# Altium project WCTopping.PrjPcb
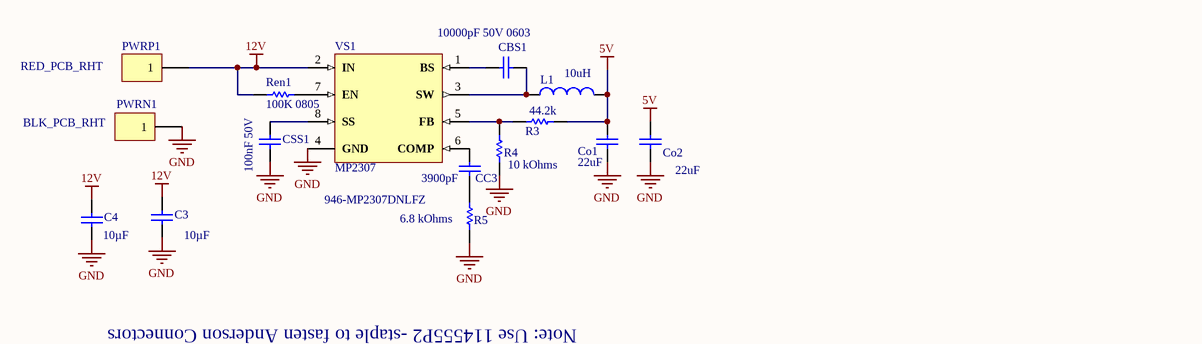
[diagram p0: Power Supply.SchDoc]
Project_Name: WC Topping; Revision: 1.2
5 sheets, 59 parts. Net scope: flat (ports and power ports of the same name join across sheets).
Board file: WCTopping.PcbDoc
Sheets:
  Power Supply.SchDoc
  Processor_Interface.SchDoc
  CAN_Interface.SchDoc
  Digital_IO.SchDoc
  Relay_IO.SchDoc

## Sheet Power Supply.SchDoc: Power Supply 5V @ 3A
size A; Engineer: H Potential; DocumentNumber: 5; Revision: 3.2; SheetNumber: 5; SheetTotal: 5

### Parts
C3  10µF  [CAPC2013X135X45ML10T25]
C4  10µF  [CAPC2013X135X45ML10T25]
CBS1  10000pF 50V 0603  [0603C_L]
CC3  3900pF  [0603C_L]
Co1  22uF  [0603C_L]
Co2  22uF  [0603C_L]
CSS1  100nF 50V  [0603C_L]
L1  10uH  [IND_1]
PWRN1  BLK_PCB_RHT  [Anderson_BLK_RHT_BOT]
PWRP1  RED_PCB_RHT  [Anderson_Red_RHT_BOT]
R3  44.2k  [0805_L]
R4  10 kOhms  [0805_L]
R5  6.8 kOhms  [0805_L]
Ren1  100K 0805  [0805_L]
VS1  MP2307  Supplier Part Number 1: 946-MP2307DNLFZ  [SOIC8N_EXP]

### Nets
5V: Co1.2 Co2.2 L1.2 R3.1
12V: C3.2 C4.2 PWRP1.1 Ren1.1 VS1.2(IN)
GND: C3.1 C4.1 Co1.1 Co2.1 CSS1.1 PWRN1.1 R4.2 R5.1 VS1.4(GND)
NetCBS1_1: CBS1.1 L1.1 VS1.3(SW)
NetCBS1_2: CBS1.2 VS1.1(BS)
NetCC3_1: CC3.1 R5.2
NetCC3_2: CC3.2 VS1.6(COMP)
NetCSS1_2: CSS1.2 VS1.8(SS)
NetR3_2: R3.2 R4.1 VS1.5(FB)
NetRen1_2: Ren1.2 VS1.7(EN)

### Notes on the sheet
- Note: Use 114555P2 -staple to fasten Anderson Connectors

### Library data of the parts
C3 C4 = CMP-2007-03541-1: Part Number: GRM21BR61E106KA73L; Manufacturer: Murata; Product Training Modules: High-Cap Multilayer Ceramic Capacitors; Catalog Drawings: GRM Series_0805_1.25; Tolerance: ±10%; Voltage - Rated: 25V; Temperature Coefficient: X5R; Online Catalog: GRM Series; Other Names: 490-5523-6
CBS1 = Cap10000pF_50V_0603: Manufacturer: Yageo; Manufacturer Part Number: CC0603KRX7R9BB103; Product Training Modules: Multilayer Ceramic Capacitors; Featured Product: Commodity Multilayer Ceramic Capacitors – CC Series; Tolerance: ±10%; Temperature Coefficient: X7R; Online Catalog: CC Series; Other Names: 311-1085-6
CC3 = Cap_0603_1: Manufacturer: Murata; Manufacturer Part Number: GRM188R71E392KA01D; Tolerance (+ or -): 10%; Voltage: 25VDC; Temp Coeff (Dielectric): X7R; Case Style: Ceramic Chip; Wire Form: Not Required; Product Length (mm): 1.6mm; Product Depth (mm): 0.8mm; Product Diameter (mm): Not Requiredmm
Co1 Co2 = Cap_0603_1: Manufacturer: Murata; Manufacturer Part Number: GRM188R60J226MEA0D; Tolerance (+ or -): 20%; Voltage: 6.3VDC; Temp Coeff (Dielectric): X5R; Case Style: Ceramic Chip; Wire Form: Not Required; Product Length (mm): 1.6mm; Product Depth (mm): 0.8mm; Product Diameter (mm): Not Requiredmm
CSS1 = Cap100nF_50V_0603: Manufacturer: Yageo; Manufacturer Part Number: CC0603ZRY5V9BB104; Capacitance: 0.10µF; Tolerance: -20%, +80%; Temperature Coefficient: Y5V (F)
L1 = Inductor: Manufacturer: Abracon; Manufacturer Part Number: ASPI-0630LR-100M-T15; Code_IEC: 1005; Rad Hard: No; Type: Power; Maximum DC Current: 4 A; Tolerance: 20 %; Maximum DC Resistance: 68 mOhm; Product Depth: 6.65 mm; Product Height: 3(Max) mm
PWRN1 = Anderson-1Pin BLK_PCB_RHT: 1 pin Anderson; Manufacturer: Anderson Power Products (APP); Manufacturer Part Number: 1377G1, 1377G2, 1327-BK,137G6-BK; Number of Positions / Contacts: 1; Voltage Rating: 600 V; Current Rating: 25 A
PWRP1 = Anderson-1Pin RED_PCB_RHT: 1 pin Anderson; Manufacturer: Anderson Power Products (APP); Manufacturer Part Number: 1377G1, 1377G2, 1327-BK,137G6-BK; Number of Positions / Contacts: 1; Voltage Rating: 600 V; Current Rating: 25 A
R3 = Res_0805: Manufacturer: Yageo; Manufacturer Part Number: RC0805FR-0744K2L; Product Training Modules: Chip Resistor; Catalog Drawings: Thick Film Resistor Side; PCN Other: RC/AC 0603/0805/1206 22/Jan/2013; HTML Datasheet: RC Series, L Suffix Datasheet.html; EDA / CAD Models: Download from Accelerated Designs; Tolerance: ±1%; Power (Watts): 0.125W, 1/8W; Temperature Coefficient: ±100ppm/°C; Online Catalog: RC0805 Series; Kits: PHC5A-KIT-ND  - RESISTOR KIT 10K-97.6K 1/8W PHC5-KIT-ND  - RESISTOR KIT 10K-97.6K 1/8W; Other Names: 311-44.2KCRCT
R4 = Res_0805: Manufacturer: Yageo; Manufacturer Part Number: RC0805FR-0710KL; Tolerance: 1 %; Power Rating: 125 mW (1/8 W); Voltage Rating: 150 V; Temperature Coefficient: 100 PPM / C
R5 = Res_0805: Manufacturer: Yageo; Manufacturer Part Number: RC0805JR-076K8L; Tolerance: 5 %; Power Rating: 125 mW (1/8 W); Voltage Rating: 150 V; Temperature Coefficient: 100 PPM / C
Ren1 = Res100K_080: Manufacturer: Panasonic / Panasonic ECG; Manufacturer Part Number: ERJ-6GEYJ104V; Rated Power: 0.125 W; Resistance: 100 kO; Tolerance (%): ±5 %; Temp Coefficient: ±200 ppm/°C
VS1 = MP2307: Manufacturer: Monolithic Power Systems (MPS); Manufacturer Part Number: MP2307DN-LF-Z; Input Voltage MAX: 23 V; Switching Frequency: 340 kHz; Output Voltage: 0.925 V to 20 V; Output Current: 3 A; Number of Outputs: 1 Output; Input Voltage MIN: 4.75 V; Supply Current: 1.3 mA; Topology: Buck

## Sheet Processor_Interface.SchDoc: Processor 40pin GPIO Interface
size A; Engineer: D Board; DocumentNumber: 1; Revision: 1.2c; SheetNumber: 1; SheetTotal: 5
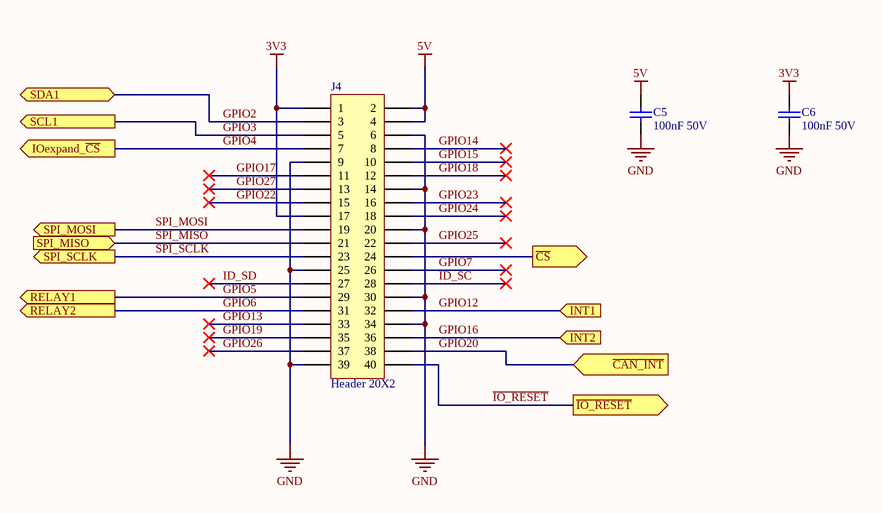
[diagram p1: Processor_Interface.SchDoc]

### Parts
C5  100nF 50V  [0603C_L]
C6  100nF 50V  [0603C_L]
J4  Header 20X2  [HDR2X20]

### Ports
INT1 (in), INT2 (in), IOexpand_~{CS} (out), RELAY1 (out), RELAY2 (out), SCL1 (out), SDA1 (bidir), SPI_MISO (in), SPI_MOSI (out), SPI_SCLK (out), ~{CAN_INT} (in), ~{CS} (out), ~{IO_RESET} (out)

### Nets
3V3: C6.2 J4.1 J4.17
5V: C5.2 J4.2 J4.4
GND: C5.1 C6.1 J4.6 J4.9 J4.14 J4.20 J4.25 J4.30 J4.34 J4.39
~{IO_RESET}: J4.40 ; port ~{IO_RESET}
~{CS}: J4.24 ; port ~{CS}
GPIO2: J4.3 ; port SDA1
GPIO3: J4.5 ; port SCL1
GPIO4: J4.7 ; port IOexpand_~{CS}
GPIO5: J4.29 ; port RELAY1
GPIO6: J4.31 ; port RELAY2
GPIO7: J4.26
GPIO12: J4.32 ; port INT1
GPIO13: J4.33
GPIO14: J4.8
GPIO15: J4.10
GPIO16: J4.36 ; port INT2
GPIO17: J4.11
GPIO18: J4.12
GPIO19: J4.35
GPIO20: J4.38 ; port ~{CAN_INT}
GPIO22: J4.15
GPIO23: J4.16
GPIO24: J4.18
GPIO25: J4.22
GPIO26: J4.37
GPIO27: J4.13
ID_SC: J4.28
ID_SD: J4.27
SPI_MISO: J4.21 ; port SPI_MISO
SPI_MOSI: J4.19 ; port SPI_MOSI
SPI_SCLK: J4.23 ; port SPI_SCLK

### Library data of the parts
C5 C6 = Cap100nF_50V_0603: as CSS1 on sheet Power Supply
J4 = Header 20X2: Header, 20-Pin, Dual row

## Sheet CAN_Interface.SchDoc: CAN Bus Interface Logic
size B; Engineer: Daisy Chain; DocumentNumber: 3; Revision: 2.3; SheetNumber: 3; SheetTotal: 5
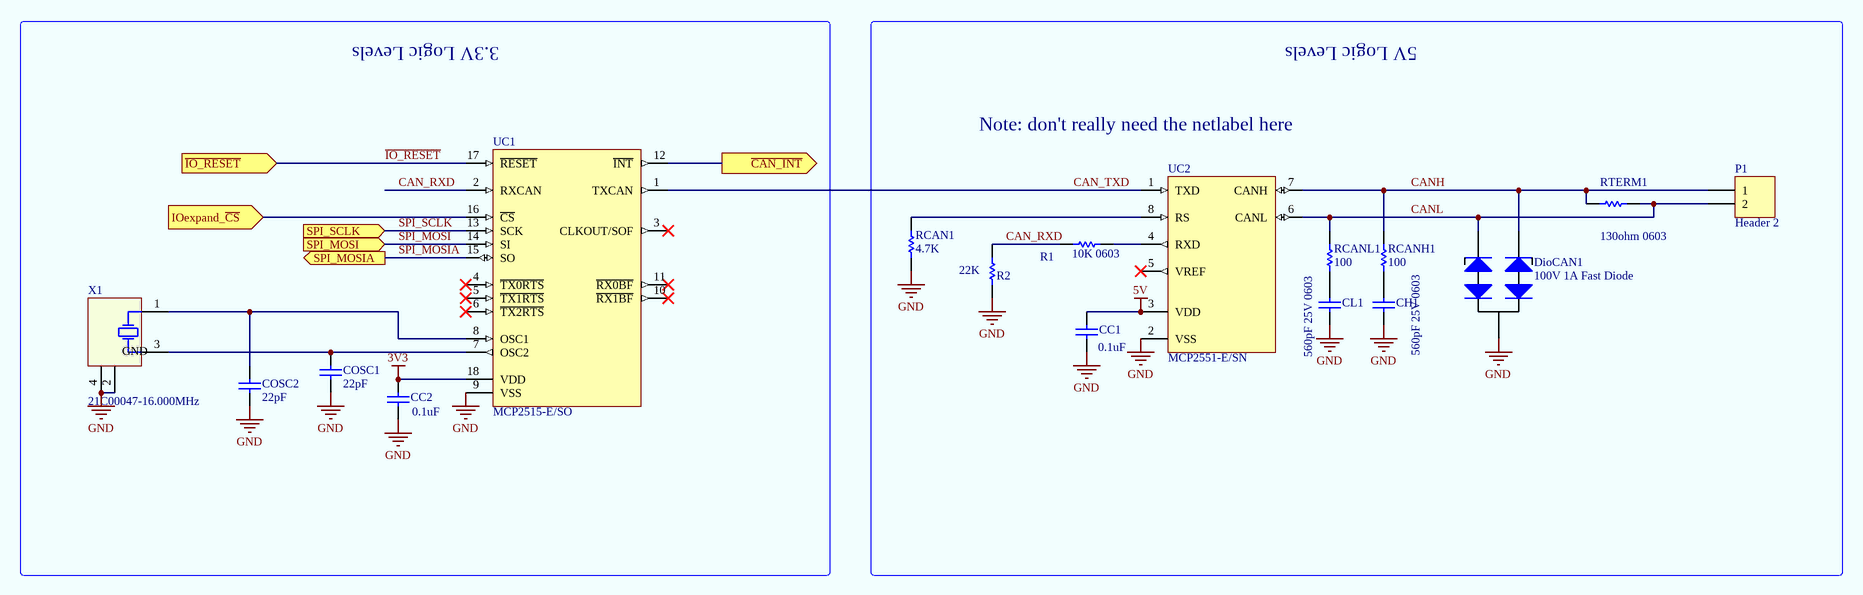
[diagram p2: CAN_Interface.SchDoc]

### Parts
CC1  0.1uF  [0603C_L]
CC2  0.1uF  [0603C_L]
CH1  560pF 25V 0603  [0603C_L]
CL1  560pF 25V 0603  [0603C_L]
COSC1  22pF  [0603C_L]
COSC2  22pF  [0603C_L]
DioCAN1  100V 1A Fast Diode  [SOT23]
P1  Header 2  [HDR1X2]
R1  10K 0603  [0603_L]
R2  22K  [0603_L]
RCAN1  4.7K  [0603_L]
RCANH1  100  [0603_L]
RCANL1  100  [0603_L]
RTERM1  130ohm 0603  [0603_L]
UC1  MCP2515-E/SO  [SOIC-SO18_M]
UC2  MCP2551-E/SN  [SOIC-SN8_N]
X1  21C00047-16.000MHz  [ITTI-21C00047-16.000MHz-4_V]

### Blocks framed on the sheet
3.3V Logic Levels: CC2 COSC1 COSC2 UC1 X1

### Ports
IOexpand_~{CS} (in), SPI_MOSI (in), SPI_MOSIA (out), SPI_SCLK (in), ~{CAN_INT} (out), ~{IO_RESET} (in)

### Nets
3V3: CC2.2 UC1.18(VDD)
5V: CC1.2 UC2.3(VDD)
GND: CC1.1 CC2.1 CH1.2 CL1.1 COSC1.1 COSC2.2 DioCAN1.3 R2.1 RCAN1.1 UC1.9(VSS) UC2.2(VSS) X1.2(GND) X1.4(GND)
~{IO_RESET}: UC1.17(~{RESET}) ; port ~{IO_RESET}
CAN_RXD: R1.2 R2.2 UC1.2(RXCAN)
CAN_TXD: UC1.1(TXCAN) UC2.1(TXD)
CANH: DioCAN1.1(A) P1.1 RCANH1.2 RTERM1.2 UC2.7(CANH)
CANL: DioCAN1.2(K) P1.2 RCANL1.2 RTERM1.1 UC2.6(CANL)
GPIO4: UC1.16(~{CS}) ; port IOexpand_~{CS}
GPIO20: UC1.12(~{INT}) ; port ~{CAN_INT}
SPI_MOSI: UC1.14(SI) ; port SPI_MOSI
SPI_MOSIA: UC1.15(SO) ; port SPI_MOSIA
SPI_SCLK: UC1.13(SCK) ; port SPI_SCLK
NetCH1_1: CH1.1 RCANH1.1
NetCL1_2: CL1.2 RCANL1.1
NetCOSC1_2: COSC1.2 UC1.7(OSC2) X1.3(XTAL)
NetCOSC2_1: COSC2.1 UC1.8(OSC1) X1.1(XTAL)
NetR1_1: R1.1 UC2.4(RXD)
NetRCAN1_2: RCAN1.2 UC2.8(RS)

Not connected (* = marked no-connect by the designer): UC1 3(CLKOUT/SOF)* 4(~{TX0RTS})* 5(~{TX1RTS})* 6(~{TX2RTS})* 10(~{RX1BF})* 11(~{RX0BF})*; UC2 5(VREF)*

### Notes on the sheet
- 5V Logic Levels
- Note: don't really need the netlabel here

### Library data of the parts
CC1 CC2 = Cap10uF_25V_0603
CH1 CL1 = Cap10uF_25V_0603: Manufacturer: Taiyo Yuden; Manufacturer Part Number: TMK316F106ZL-T; Catalog Drawings: xMK Series_1206_1.6; Capacitance: 10µF; Tolerance: -20%, +80%; Temperature Coefficient: Y5V (F); Online Catalog: M Series; Other Names: 587-1353-6
COSC1 COSC2 = Cap100nF_50V_0603: Manufacturer: Murata; Manufacturer Part Number: GRM1885C1H220JA01D; Capacitance: 22; Voltage Rating: 50; Tolerance: 5; Type (Capacitors): C0G
DioCAN1 = PESD1CAN: High Conductance Fast Diode; Manufacturer: ON Semiconductor; Manufacturer Part Number: MUR110RLG; Diode Case Style: DO-204AL; Diode Configuration: Single; Diode Type: Fast Recovery; Forward Surge Current Ifsm Max: 35A; Forward Voltage VF Max: 1.25V; No. of Pins: 2; Reverse Recovery Time trr Max: 75ns; SVHC: No SVHC (16-Jun-2014)
P1 = Header 2: Header, 2-Pin
R1 = Res4K99_0603: Manufacturer: Yageo; Manufacturer Part Number: RT0603DRD074K99L; Tolerance: ±0.5%; Power (Watts): 0.1W, 1/10W; Temperature Coefficient: ±25ppm/°C
R2 = Res_0603: Manufacturer: Yageo; Manufacturer Part Number: RT0603DRD0722KL; Resistance: 22 kOhms; Tolerance: 0.5 %; Power Rating: 100 mW; Temperature Coefficient: 25 PPM / C; Voltage Rating: 75 V; Unit Weight: 0.000071 oz
RCAN1 = Res4K99_0603: Manufacturer: Yageo; Manufacturer Part Number: RT0603DRD074K99L; Resistance (Ohms): 4.99k; Tolerance: ±0.5%; Power (Watts): 0.1W, 1/10W; Temperature Coefficient: ±25ppm/°C
RCANH1 RCANL1 = Res330_0603: Manufacturer: Yageo; Manufacturer Part Number: RC0603JR-07330RL; Resistance (Ohms): 330; Tolerance: ±5%; Power (Watts): 0.1W, 1/10W; Temperature Coefficient: ±100ppm/°C
RTERM1 = Res330_0603
UC1 = CMP-0186-00035-2: Stand-Alone CAN Controller With SPI Interface, 18-Pin SOIC, Extended Temperature
UC2 = CMP-0186-00038-2: High-Speed CAN Transceiver, 8-Pin SOIC, Extended Temperature
X1 = CMP-0464-00001-2: Crystal, 16 MHz, -30 to 85 degC, 3.2 x 2.5 x 0.9 mm SMD; Manufacturer: ITTI; Frequency Tolerance: +/-20 ppm; Load Capacitance: 10 pF; Drive Level: 100 max. uw; Nominal Frequency: 16 MHz; Overtone order: Fundamental

## Sheet Digital_IO.SchDoc: Digital IO Expansion Logic
size B; Engineer: Z Transform; DocumentNumber: 2; Revision: 1.1; SheetNumber: 2; SheetTotal: 5
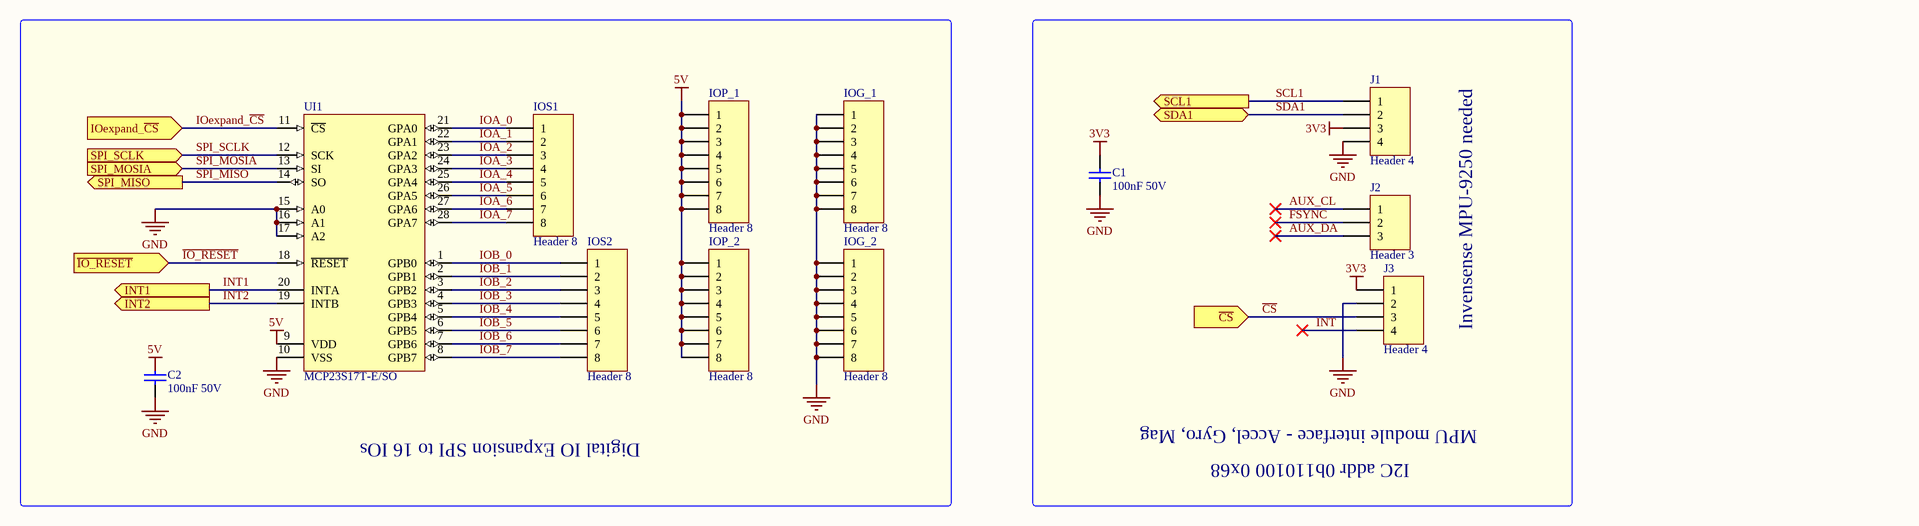
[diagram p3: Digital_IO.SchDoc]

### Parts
C1  100nF 50V  [0603C_L]
C2  100nF 50V  [0603C_L]
IOG_1  Header 8  [HDR1X8]
IOG_2  Header 8  [HDR1X8]
IOP_1  Header 8  [HDR1X8]
IOP_2  Header 8  [HDR1X8]
IOS1  Header 8  [HDR1X8]
IOS2  Header 8  [HDR1X8]
J1  Header 4  [HDR1X4]
J2  Header 3  [HDR1X3]
J3  Header 4  [HDR1X4]
UI1  MCP23S17T-E/SO  [SOIC-SO28_L]

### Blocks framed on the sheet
Digital IO Expansion SPI to 16 IOs: C2 IOG_1 IOG_2 IOP_1 IOP_2 IOS1 IOS2 UI1

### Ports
INT1 (out), INT2 (out), IOexpand_~{CS} (in), SCL1 (out), SDA1 (bidir), SPI_MISO (out), SPI_MOSIA (in), SPI_SCLK (in), ~{CS} (in), ~{IO_RESET} (in)

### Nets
3V3: C1.2 J1.3 J3.1
5V: IOP_1.1 IOP_1.2 IOP_1.3 IOP_1.4 IOP_1.5 IOP_1.6 IOP_1.7 IOP_1.8 IOP_2.1 IOP_2.2 IOP_2.3 IOP_2.4 IOP_2.5 IOP_2.6 IOP_2.7 IOP_2.8 UI1.9(VDD)
GND: C1.1 C2.1 IOG_1.1 IOG_1.2 IOG_1.3 IOG_1.4 IOG_1.5 IOG_1.6 IOG_1.7 IOG_1.8 IOG_2.1 IOG_2.2 IOG_2.3 IOG_2.4 IOG_2.5 IOG_2.6 IOG_2.7 IOG_2.8 J1.4 J3.2 UI1.10(VSS) UI1.15(A0) UI1.16(A1) UI1.17(A2)
~{IO_RESET}: UI1.18(~{RESET}) ; port ~{IO_RESET}
AUX_CL: J2.1
AUX_DA: J2.3
~{CS}: J3.3 ; port ~{CS}
FSYNC: J2.2
INT: J3.4
INT1: UI1.20(INTA) ; port INT1  [project net GPIO12]
INT2: UI1.19(INTB) ; port INT2  [project net GPIO16]
IOA_0: IOS1.1 UI1.21(GPA0)
IOA_1: IOS1.2 UI1.22(GPA1)
IOA_2: IOS1.3 UI1.23(GPA2)
IOA_3: IOS1.4 UI1.24(GPA3)
IOA_4: IOS1.5 UI1.25(GPA4)
IOA_5: IOS1.6 UI1.26(GPA5)
IOA_6: IOS1.7 UI1.27(GPA6)
IOA_7: IOS1.8 UI1.28(GPA7)
IOB_0: IOS2.1 UI1.1(GPB0)
IOB_1: IOS2.2 UI1.2(GPB1)
IOB_2: IOS2.3 UI1.3(GPB2)
IOB_3: IOS2.4 UI1.4(GPB3)
IOB_4: IOS2.5 UI1.5(GPB4)
IOB_5: IOS2.6 UI1.6(GPB5)
IOB_6: IOS2.7 UI1.7(GPB6)
IOB_7: IOS2.8 UI1.8(GPB7)
IOexpand_~{CS}: UI1.11(~{CS}) ; port IOexpand_~{CS}  [project net GPIO4]
SCL1: J1.1 ; port SCL1  [project net GPIO3]
SDA1: J1.2 ; port SDA1  [project net GPIO2]
SPI_MISO: UI1.14(SO) ; port SPI_MISO
SPI_MOSIA: UI1.13(SI) ; port SPI_MOSIA
SPI_SCLK: UI1.12(SCK) ; port SPI_SCLK

Not connected (* = marked no-connect by the designer): C2 2

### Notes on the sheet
- Invensense MPU-9250 needed
- MPU module interface - Accel, Gyro, Mag
- I2C addr 0b110100 0x68
- Labels drawn without touching a wire or pin: 5V

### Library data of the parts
C1 C2 = Cap100nF_50V_0603: as CSS1 on sheet Power Supply
IOG_1 IOG_2 IOP_1 IOP_2 IOS1 IOS2 = Header 8: Header, 8-Pin
J1 J3 = Header 4: Header, 4-Pin
J2 = Header 3: Header, 3-Pin
UI1 = CMP-0186-00131-2: 16-Bit I/O Expander with Serial Interface, 28-Pin SOIC, Extended Temperature, Tape and Reel

## Sheet Relay_IO.SchDoc: 12V Solenoid Relay Logic
size A; Engineer: S Circuit; DocumentNumber: 4; Revision: 1.2; SheetNumber: 4; SheetTotal: 5
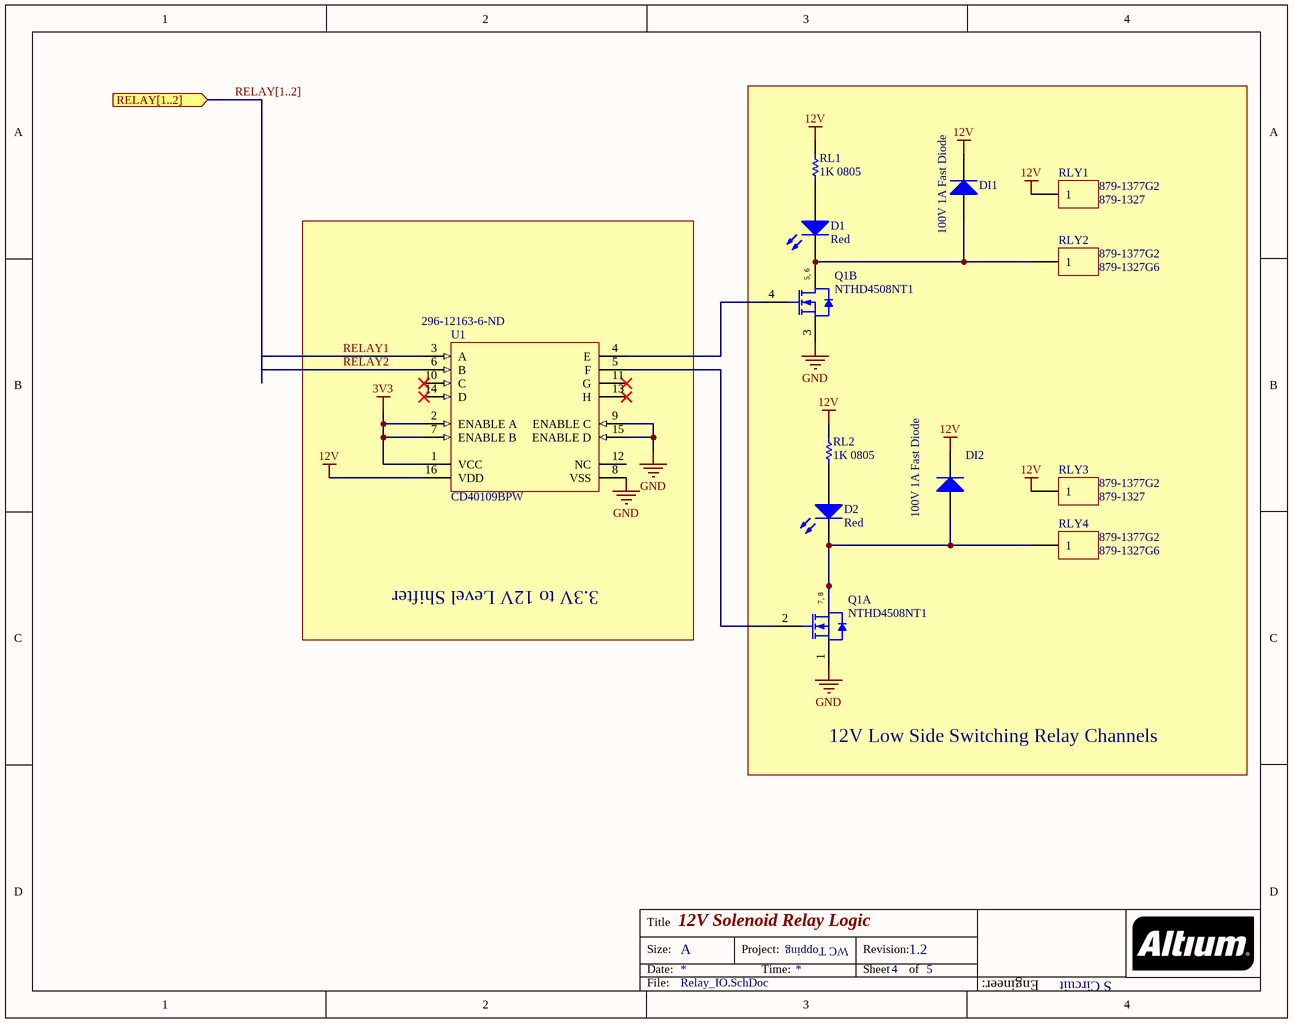
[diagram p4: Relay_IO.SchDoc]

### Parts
D1  Color: Red  [0603_A]  (hidden comment: LED Red)
D2  Color: Red  [0603_A]  (hidden comment: LED Red)
DI1  100V 1A Fast Diode  [DO-35]
DI2  100V 1A Fast Diode  [DO-35]
Q1  NTHD4508NT1  [ONSC-CHIPFET-8-1206A-03_S2_V]  (parts A,B of 2)
RL1  1K 0805  [0805_L]
RL2  1K 0805  [0805_L]
RLY1  Supplier Part Number 1: 879-1377G2  Supplier Part Number 2: 879-1327  [Anderson_Red_RHT_BOT]  (hidden comment: Anderson-1Pin RED_PCB_RHT)
RLY2  Supplier Part Number 1: 879-1377G2  Supplier Part Number 2: 879-1327G6  [Anderson_BLK_RHT_BOT]  (hidden comment: Anderson-1Pin BLK_PCB_RHT)
RLY3  Supplier Part Number 1: 879-1377G2  Supplier Part Number 2: 879-1327  [Anderson_Red_RHT_BOT]  (hidden comment: Anderson-1Pin RED_PCB_RHT)
RLY4  Supplier Part Number 1: 879-1377G2  Supplier Part Number 2: 879-1327G6  [Anderson_BLK_RHT_BOT]  (hidden comment: Anderson-1Pin BLK_PCB_RHT)
U1  CD40109BPW  Supplier Part Number 1: 296-12163-6-ND  [PW0016A_M]

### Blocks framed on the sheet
12V Low Side Switching Relay Channels: D1 D2 DI1 DI2 Q1 RL1 RL2 RLY1-RLY4
3.3V to 12V Level Shifter: U1

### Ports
RELAY[1..2] (in)

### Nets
3V3: U1.1(VCC) U1.2(ENABLE_A) U1.7(ENABLE_B)
12V: DI1.2(K) DI2.2(K) RL1.2 RL2.2 RLY1.1 RLY3.1 U1.16(VDD)
GND: Q1.1(S1) Q1.3(S2) U1.8(VSS) U1.9(ENABLE_C) U1.15(ENABLE_D)
RELAY1: U1.3(A)
RELAY2: U1.6(B)
NetD1_1: D1.1(K) DI1.1(A) Q1.5(D2) Q1.6(D2) RLY2.1
NetD1_2: D1.2(A) RL1.1
NetD2_1: D2.1(K) DI2.1(A) Q1.7(D1) Q1.8(D1) RLY4.1
NetD2_2: D2.2(A) RL2.1
NetQ1_2: Q1.2(G1) U1.5(F)
NetQ1_4: Q1.4(G2) U1.4(E)

Not connected (* = marked no-connect by the designer): U1 10(C)* 11(G)* 12(NC) 13(H)* 14(D)*

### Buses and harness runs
bus RELAY[1..2] = port RELAY[1..2]

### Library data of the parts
D1 D2 = LED_Red0603: SMD mono-color Chip LED, WL-SMCW, Red; Manufacturer: Wurth Electronics Inc; Manufacturer Part Number: 150060RS75000; Lens Color: Colorless; Lens Transparency: Clear; Millicandela Rating: 250mcd; Lens Style/Size: Rectangle with Flat Top, 1.10mm x 0.70mm; Voltage - Forward (Vf) (Typ): 2V; Current - Test: 20mA; Viewing Angle: 140°; Wavelength - Dominant: 625nm; Wavelength - Peak: 630nm
DI1 DI2 = Diode 1N4148: High Conductance Fast Diode; Manufacturer: ON Semiconductor; Manufacturer Part Number: MUR110RLG; Diode Case Style: DO-204AL; Diode Configuration: Single; Diode Type: Fast Recovery; Forward Surge Current Ifsm Max: 35A; Forward Voltage VF Max: 1.25V; No. of Pins: 2; Reverse Recovery Time trr Max: 75ns; SVHC: No SVHC (16-Jun-2014)
Q1 = NTHD4508NT1: Power MOSFET, 20 V, 4.1 A, Dual N-Channel, 8-Pin CHIPFET, Tape and Reel; Manufacturer: On Semiconductor; Manufacturer Part Number: NTHD4508NT1G; V(BR)DSS Min (V): 20; VGS(th) Max (V): 1.2; ID Max (A): 4.1; Ciss Typ (pF): 180; Crss Typ (pF): 25; Qrr Typ (nC): 6; Coss Typ (pF): 80; Channel Polarity: N Channel; VGS Max (V): 12; FET Type: 2 N-Channel (Dual); FET Feature: Logic Level Gate; Drain to Source Voltage (Vdss): 20V; Current - Continuous Drain (Id) @ 25°C: 3A; Rds On (Max) @ Id, Vgs: 75 mOhm @ 3.1A, 4.5V; Vgs(th) (Max) @ Id: 1.2V @ 250µA; Gate Charge (Qg) @ Vgs: 4nC @ 4.5V; Input Capacitance (Ciss) @ Vds: 180pF @ 10V; Power - Max: 1.13W
RL1 RL2 = Res1K_0805: Manufacturer: Panasonic Electronic Components; Manufacturer Part Number: ERJ-6GEYJ102V; Tolerance: ±5%; Power (Watts): 0.125W, 1/8W; Temperature Coefficient: ±200ppm/°C
RLY1 RLY3 = Anderson-1Pin RED_PCB_RHT: as PWRP1 on sheet Power Supply
RLY2 RLY4 = Anderson-1Pin BLK_PCB_RHT: as PWRN1 on sheet Power Supply
U1 = CMP-1527-00010-2: CMOS Quad Low-to-High Voltage Level Shifter, 3 to 18 V, -55 to 125 degC, 16-Pin TSSOP (PW16), RoHS, Tube; Manufacturer: Texas Instruments; Manufacturer Part Number: CD40109BPWR; Number of Bits: 4; VSS: 3 to 18 V; Propagation Delay: 240 ns Max.; Logic Function: Level Shifter, 3-State; Number of Outputs/Channel: 1; Differential - Input:Output: No/No; Propagation Delay (Max): 240ns; Voltage - Supply: 3 V ~ 18 V; Dynamic Catalog: 4000B; Other Names: 296-12163-6

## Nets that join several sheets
3V3: Processor_Interface (C6.2 J4.1 J4.17), CAN_Interface (CC2.2 UC1.18), Digital_IO (C1.2 J1.3 J3.1), Relay_IO (U1.1 U1.2 U1.7)
5V: Power Supply (Co1.2 Co2.2 L1.2 R3.1), Processor_Interface (C5.2 J4.2 J4.4), CAN_Interface (CC1.2 UC2.3), Digital_IO (17 pins)
12V: Power Supply (5 pins), Relay_IO (7 pins)
GND: Power Supply (9 pins), Processor_Interface (10 pins), CAN_Interface (13 pins), Digital_IO (24 pins), Relay_IO (5 pins)
~{IO_RESET}: Processor_Interface (J4.40), CAN_Interface (UC1.17), Digital_IO (UI1.18)
~{CS}: Processor_Interface (J4.24), Digital_IO (J3.3)
GPIO2: Processor_Interface (J4.3), Digital_IO (J1.2)
GPIO3: Processor_Interface (J4.5), Digital_IO (J1.1)
GPIO4: Processor_Interface (J4.7), CAN_Interface (UC1.16), Digital_IO (UI1.11)
GPIO12: Processor_Interface (J4.32), Digital_IO (UI1.20)
GPIO16: Processor_Interface (J4.36), Digital_IO (UI1.19)
GPIO20: Processor_Interface (J4.38), CAN_Interface (UC1.12)
SPI_MISO: Processor_Interface (J4.21), Digital_IO (UI1.14)
SPI_MOSI: Processor_Interface (J4.19), CAN_Interface (UC1.14)
SPI_MOSIA: CAN_Interface (UC1.15), Digital_IO (UI1.13)
SPI_SCLK: Processor_Interface (J4.23), CAN_Interface (UC1.13), Digital_IO (UI1.12)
